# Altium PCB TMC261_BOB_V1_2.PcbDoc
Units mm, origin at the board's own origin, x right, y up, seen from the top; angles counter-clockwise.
Board outline 38.1 x 25.4 mm, 4 copper layers (Top, GND1, GND2, Bottom), stack 0.704 mm thick; 27 components, 23 nets, 90 pads, 69 vias.
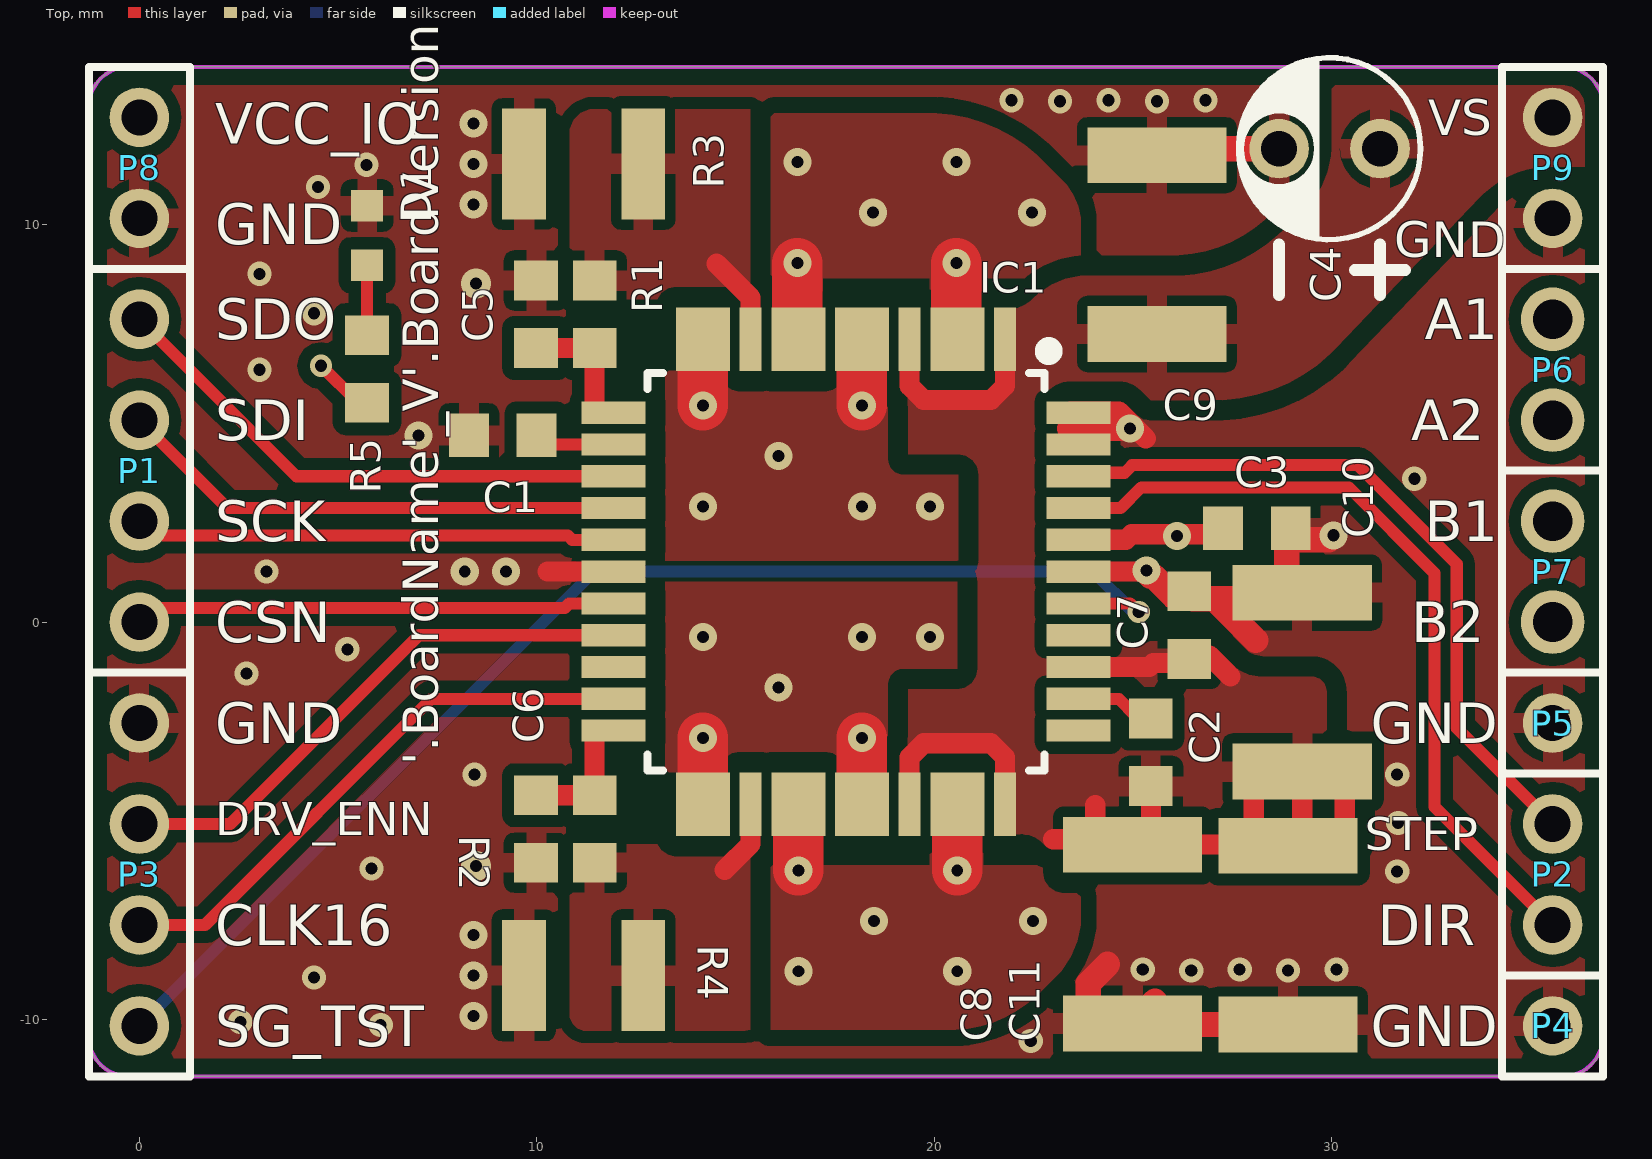
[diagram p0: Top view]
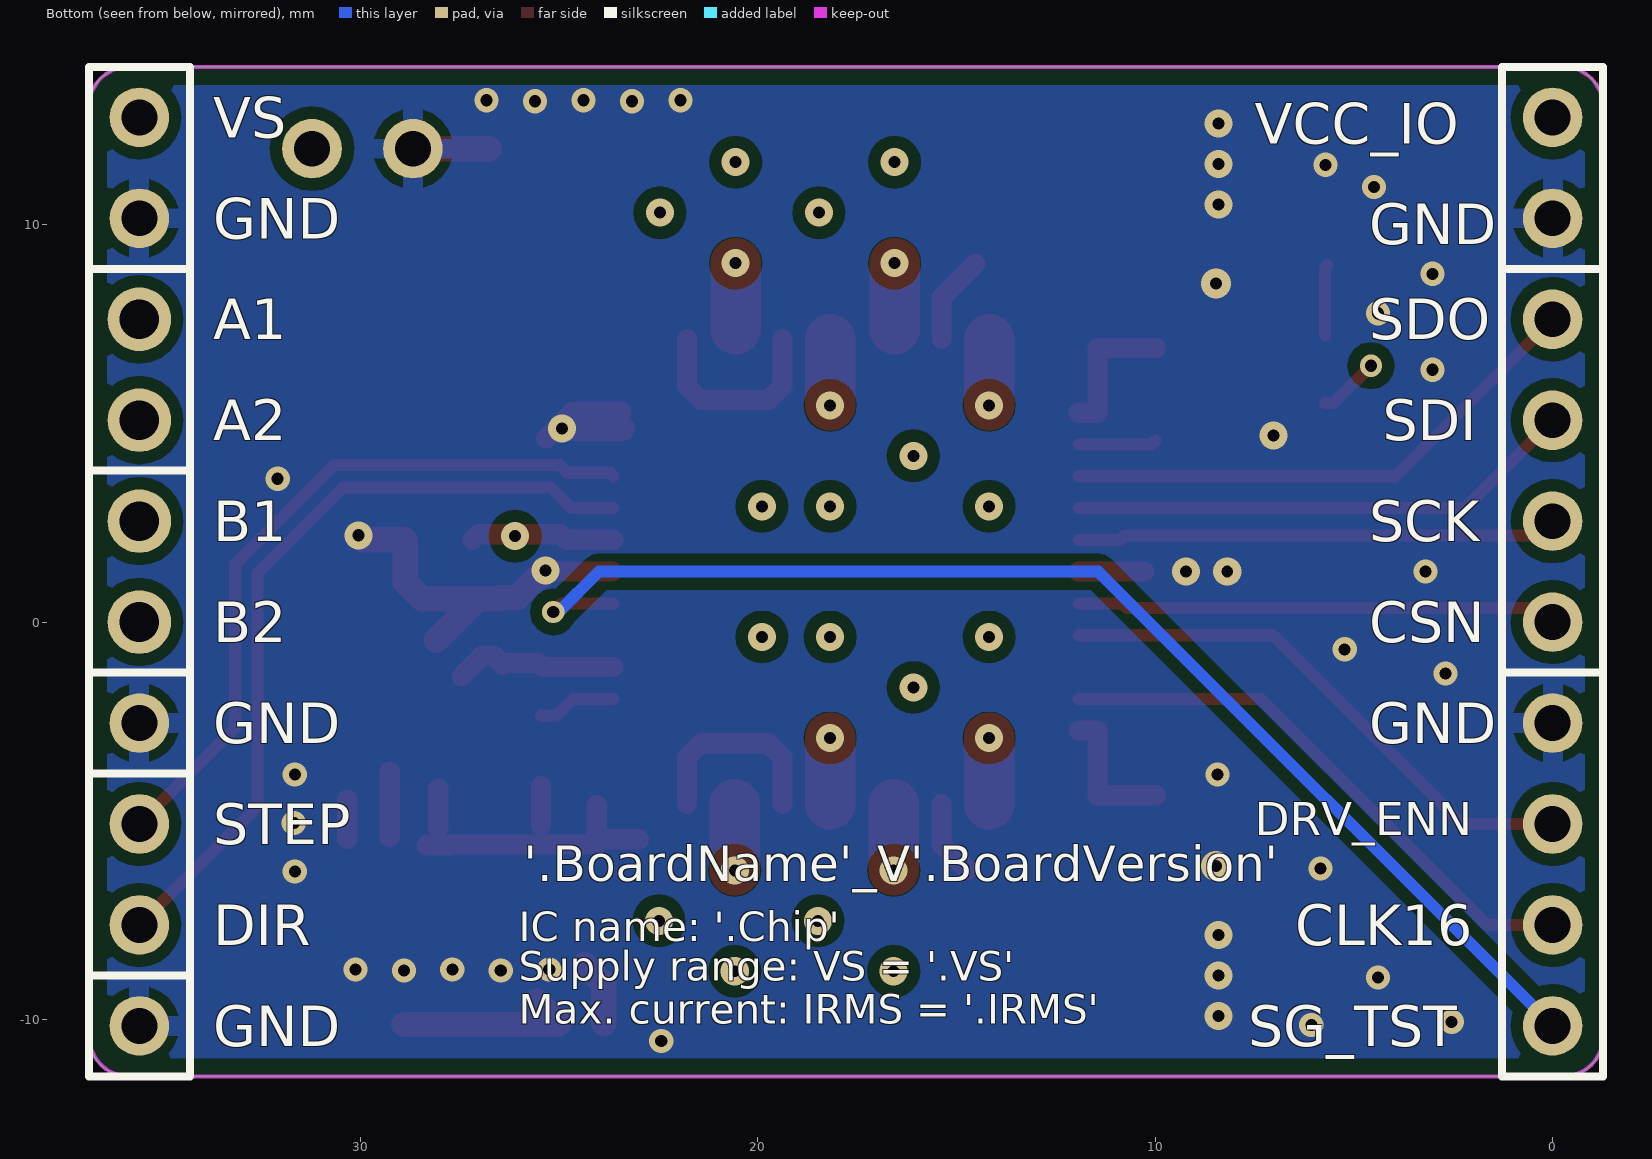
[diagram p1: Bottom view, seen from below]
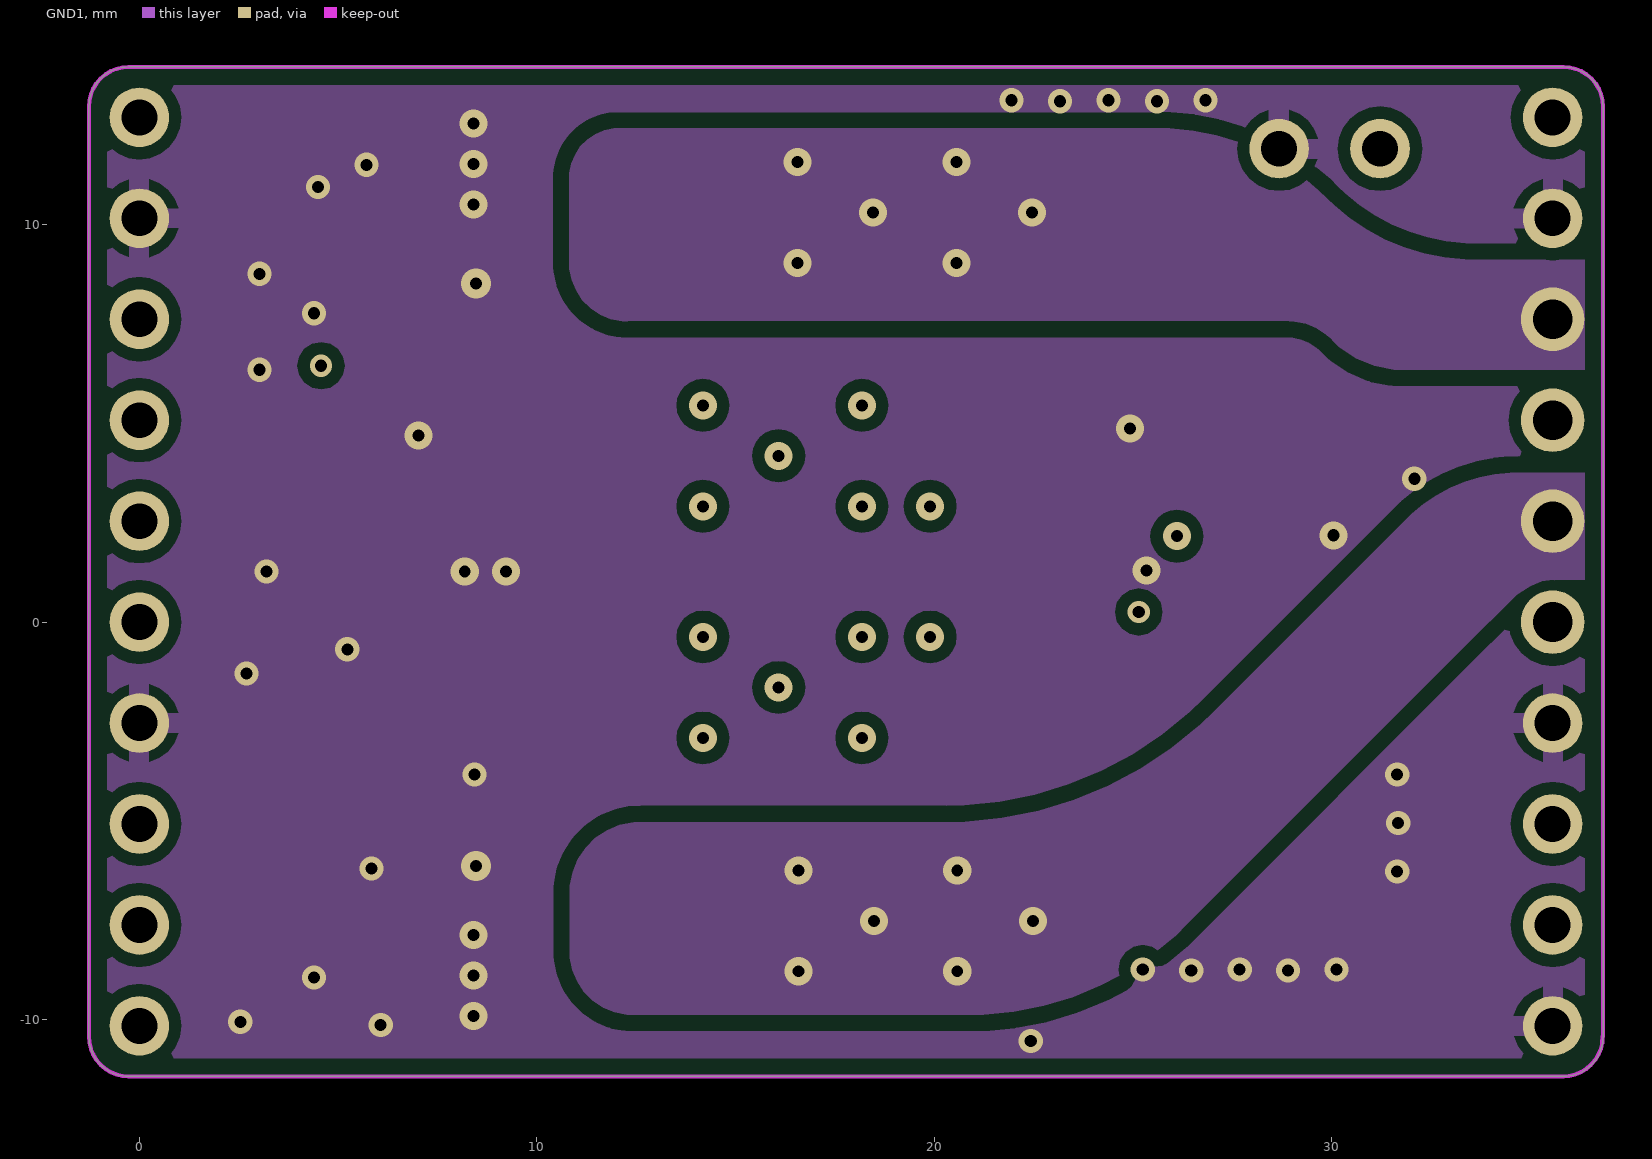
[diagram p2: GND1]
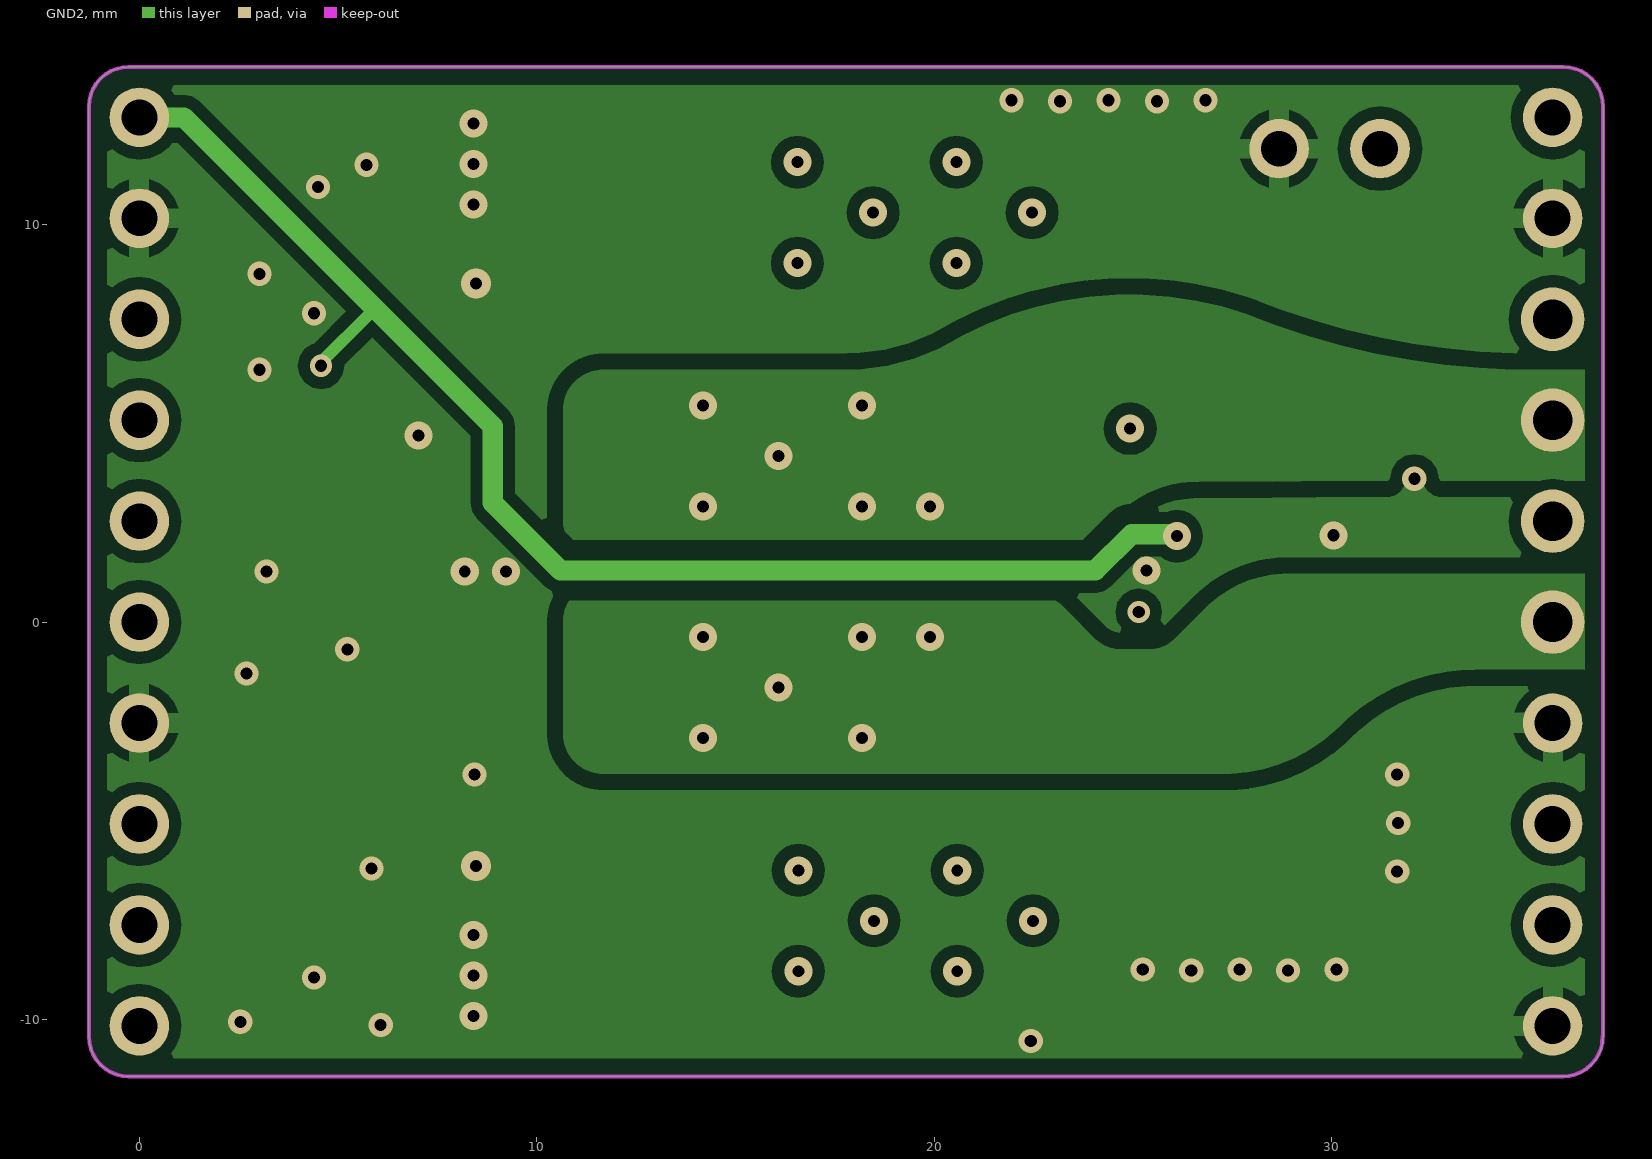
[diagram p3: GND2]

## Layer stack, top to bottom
Top Solder: solder mask 0.0102, Solder Resist, Dk 3.5
Top: signal copper 0.035
Dielectric 1: core 0.2, FR-4, Dk 4.8
GND1: signal copper 0.0175
Dielectric 2: prepreg 0.127, FR-4, Dk 4.2
GND2: signal copper 0.0356
Dielectric4: core 0.254, FR-4, Dk 4.2
Bottom: signal copper 0.035
Bottom Solder: solder mask 0.0102, Solder Resist, Dk 3.5

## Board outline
-1.27,-10.43 -1.27,12.97 cw(c-0.27,12.97) -0.27,13.97 35.83,13.97 cw(c35.83,12.97) 36.83,12.97 36.83,-10.43 cw(c35.83,-10.43) 35.83,-11.43 -0.27,-11.43 cw(c-0.27,-10.43)

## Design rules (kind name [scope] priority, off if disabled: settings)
Clearance Motor_Output_to_GND_Clearance [InNetClass('MotorOutput') vs InNet('GND')] p1: gap=0.305 ignorepadtopadclearanceinfootprint=TRUE except(0: Arc-Hole Track-Hole SMDPad-Hole THPad-Hole Via-Hole Fill-Hole Poly-Hole Region-Hole Text-Hole; 0.406: Fill-Fill Fill-Poly Fill-Region Poly-Poly Poly-Region Region-Region)
Clearance BoardOutlineClearance [OnLayer('Keep-Out Layer')] p2: gap=0.4 ignorepadtopadclearanceinfootprint=FALSE except(0: Arc-Hole Track-Hole SMDPad-Hole THPad-Hole Via-Hole Fill-Hole Poly-Hole Region-Hole Text-Hole)
Clearance PinheaderToKeepoutClearance [InComponentClass('Pinheader') vs OnLayer('Keep-Out Layer')] p3: gap=0.203 ignorepadtopadclearanceinfootprint=FALSE except(0: Arc-Hole Track-Hole SMDPad-Hole THPad-Hole Via-Hole Fill-Hole Poly-Hole Region-Hole Text-Hole)
Clearance IC1_Clearance_PadToPad_1 [InComponent('IC1') and IsPad vs InComponent('IC1') and IsPad] p4: gap=0.152 ignorepadtopadclearanceinfootprint=FALSE except(0: Arc-Hole Track-Hole SMDPad-Hole THPad-Hole Via-Hole Fill-Hole Poly-Hole Region-Hole Text-Hole)
Clearance IC1_PintoTraceClearance [InComponent('IC1') and IsPad vs Istrack] p5: gap=0.254 ignorepadtopadclearanceinfootprint=FALSE except(0: Arc-Hole Track-Hole SMDPad-Hole THPad-Hole Via-Hole Fill-Hole Poly-Hole Region-Hole Text-Hole)
Clearance MotorOutput_Clearance_1 [InNetClass('MotorOutput') vs OnLayer('Keep-Out Layer') AND IsWire and (not OnLayer('GND1')) and (not OnLayer('GND2'))] p6: gap=0.305 ignorepadtopadclearanceinfootprint=TRUE except(0: Arc-Hole Track-Hole SMDPad-Hole THPad-Hole Via-Hole Fill-Hole Poly-Hole Region-Hole Text-Hole)
Clearance MotorOutput_Clearance [InNetClass('MotorOutput') vs not (OnLayer('Keep-Out Layer') and InComponent('IC1') and IsPad)] p7: gap=0.508 ignorepadtopadclearanceinfootprint=TRUE except(0: Arc-Hole Track-Hole SMDPad-Hole THPad-Hole Via-Hole Fill-Hole Poly-Hole Region-Hole Text-Hole; 0.152: Track-Track; 0.254: THPad-Poly)
Clearance VM_Clearance [InNet('+VS') AND (NOT IsPad) vs not (InComponent('IC1'))] p8: gap=0.508 ignorepadtopadclearanceinfootprint=TRUE except(0: Arc-Hole Track-Hole SMDPad-Hole THPad-Hole Via-Hole Fill-Hole Poly-Hole Region-Hole Text-Hole; 0.29: Track-Track; 0.3: SMDPad-Poly)
Clearance "Fiducial Clearance" [HasFootprint('FIDUCIAL_40MIL')] p9 off: gap=0.66 ignorepadtopadclearanceinfootprint=FALSE except(0: Arc-Hole Track-Hole SMDPad-Hole THPad-Hole Via-Hole Fill-Hole Poly-Hole Region-Hole Text-Hole)
Clearance "Mounting Hole Clearance" [(HoleDiameter >= 110) And  IsPad  And ((PadYSize_AllLayers - HoleDiameter)  <=  1)] p10 off: gap=0.762 ignorepadtopadclearanceinfootprint=FALSE except(0: Arc-Hole Track-Hole SMDPad-Hole THPad-Hole Via-Hole Fill-Hole Poly-Hole Region-Hole Text-Hole)
Clearance [All vs NOT InComponent('IC1')] p11: gap=0.305 ignorepadtopadclearanceinfootprint=FALSE except(0: Arc-Hole Track-Hole SMDPad-Hole THPad-Hole Via-Hole Fill-Hole Poly-Hole Region-Hole Text-Hole; 0.254: Track-Track)
ComponentClearance IC1_to_series_sense_resistors_Clearance [inComponent('IC1') vs inComponent('R1') or inComponent('R2')] p1: gap=0 collisioncheckmode=3 verticalgap=2540 showdistances=FALSE
ComponentClearance Pinheader2PinheaderClearance [InComponentClass('Pinheader') vs InComponentClass('Pinheader')] p2: gap=0 collisioncheckmode=3 verticalgap=0 showdistances=FALSE
ComponentClearance [All] p3: gap=0.254 collisioncheckmode=3 verticalgap=0.102 showdistances=FALSE
DiffPairsRouting [All] p1 off: maxlimit=0.254 minlimit=0.191 mostfreqgap=0.254 toplayer_prefgap=0.191 toplayer_minwidth=0.191 toplayer_maxwidth=0.191 toplayer_prefwidth=0.191 midlayer1_prefgap=0.191 midlayer1_minwidth=0.191 midlayer1_maxwidth=0.191 midlayer1_prefwidth=0.191 midlayer2_mingap=0.254 midlayer2_minwidth=0.381 midlayer2_maxwidth=0.381 midlayer2_prefwidth=0.381 bottomlayer_prefgap=0.191 bottomlayer_minwidth=0.191 bottomlayer_maxwidth=0.191 bottomlayer_prefwidth=0.191 maxuncoupledlength=12.7
HoleSize [All] p1: absolutevalues=TRUE maxlimit=2540 minlimit=0.3 maxpercent=80.000 minpercent=20.000
HoleToHoleClearance [All] p1: gap=0.203 allowstackedmicrovias=TRUE
MatchedLengths "SD_CARD MatchedLengths" [InNetClass('SD_CARD')] p1: tolerance=0.254 checknetsindiffpair=FALSE checkdiffpairvsdiffpair=TRUE checkxsignals=TRUE checkothers=TRUE
MinimumAnnularRing MinimumViaAnnualRing [All] p1: minimumring=0.125
MinimumSolderMaskSliver STM32_MinimumSolderMaskSliver [(InComponent('STM1') AND InComponent('STM2')) vs (InComponent('STM1') AND InComponent('STM2'))] p1: minsoldermaskwidth=0.025
MinimumSolderMaskSliver USB_HUB_MinimumSolderMaskSliver [InComponent('USB_HUB')] p2: minsoldermaskwidth=0.025
MinimumSolderMaskSliver [All] p3 off: minsoldermaskwidth=0.038
PasteMaskExpansion TestPadPasteMaskExpansion [HasFootprint('SMD_TP_2X2_ROUND')] p1: expansion=-2
PasteMaskExpansion [All] p2: expansion=0
PolygonConnect VM_IC1_ConnectStyle [InNet('+VS') AND (InComponent('IC1') or InComponent('P9'))] p1: connectstyle=Direct reliefconductorwidth=0.508 reliefentries=4 polygonreliefangle="90 Angle" airgapwidth=0.203
PolygonConnect VM_ViaConnectStyle_1 [InNet('VM') AND IsVia] p2: connectstyle=Direct reliefconductorwidth=0.508 reliefentries=4 polygonreliefangle="90 Angle" airgapwidth=0.203
PolygonConnect MotorPowerConnectStyle [InNetClass('MotorOutput') vs not IsTrack] p3: connectstyle=Direct reliefconductorwidth=0.254 reliefentries=4 polygonreliefangle="90 Angle" airgapwidth=0.254
PolygonConnect ThermalVias [IsVia] p4: connectstyle=Direct reliefconductorwidth=0.254 reliefentries=4 polygonreliefangle="90 Angle" airgapwidth=0.254
PolygonConnect [All] p5: connectstyle=Relief reliefconductorwidth=0.508 reliefentries=4 polygonreliefangle="90 Angle" airgapwidth=0.254
RoutingVias GND_RoutingVias [InNet('GND')] p1: holewidth=0.305 width=0.706 viastyle="Through Hole" minholewidth=0.305 minwidth=0.559 maxholewidth=0.305 maxwidth=1.27
RoutingVias [All] p2: holewidth=0.305 width=0.559 viastyle="Through Hole" minholewidth=0.305 minwidth=0.559 maxholewidth=0.305 maxwidth=1.27
ShortCircuit [All] p1 off: allowed=FALSE
SilkToBoardRegionClearance [All] p1 off:
SilkToSilkClearance [All] p1 off: silktosilkclearance=0.254
SilkToSolderMaskClearance [IsPad] p1 off: minsilkscreentomaskgap=0.254 clearancetoexposedcopper=TRUE
SolderMaskExpansion FiducialSolderMaskExpansion [HasFootprint('FIDUCIAL_40MIL')] p1: expansion=0.66
SolderMaskExpansion [All] p2: expansion=0.102
UnRoutedNet [All] p1 off:
Width Other_Width [All] p1: maxlimit=2540 minlimit=0.203 preferedwidth=0.3 minimp=50.000000 maximp=50.000000 favimp=50.000000
19 further rules are at their usual default settings.

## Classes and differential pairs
net class MotorOutput: OA1 OA2 OB1 OB2
differential pair class USB_DIFF: STM_USB STM_USB_D
component class Pinheader: P1 P2 P3 P4 P5 P6 P7 P8 P9

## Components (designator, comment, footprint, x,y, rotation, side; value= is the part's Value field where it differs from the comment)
C1 "470nF/16V/10%" C0603 9.144,4.699 r180 top
C2 "100nF/100V/10%" C0603 25.451,-3.277 r270 top
C3 "100nF/50V/20%" C0603 28.118,2.362 r180 top
C4 "Cap Pol1" EXT_POL_CAP_FLIPPED 31.217,11.913 r90 top value=TBD
C5 "10nF/100V/10%" C0603 9.982,7.747 r270 top
C6 "10nF/100V/10%" C0603 9.982,-5.207 r90 top
C7 "100nF/100V/10%" C0603 26.416,-0.076 r270 top
C8 "10uF/100V/20%" CKG45NX7S2A106M500JH 24.994,-7.849 r90 top
C9 "10uF/100V/20%" CKG45NX7S2A106M500JH 25.603,9.5 r270 top
C10 "10uF/100V/20%" CKG45NX7S2A106M500JH 29.261,-1.508 r270 top
C11 "10uF/100V/20%" CKG45NX7S2A106M500JH 28.905,-7.874 r90 top
D1 "LED, Blue, SMD, 20mA, 2.8V, 465 nm" LED_0603 5.73,9.728 r90 top
IC1 "TMC261" TMC26X_PQFP44_0.8_10X10_TMC236 17.78,1.27 r180 top value=TMC261-PA
P1 "SPI" 4_PIN_THT 0,0 r0 top
P2 "STEP/DIR" 2_PIN_THT 35.56,-5.08 r180 top
P3 "MISC" 4_PIN_THT 0,-10.16 r0 top
P4 "GND" TH_PIN 35.56,-10.16 r0 top
P5 "GND" TH_PIN 35.56,-2.54 r0 top
P6 "OA" 2_PIN_THT_1MM_HOLE 35.56,5.08 r0 top
P7 "OB" 2_PIN_THT_1MM_HOLE 35.56,0 r0 top
P8 "VCC_IO" 2_PIN_THT 0,10.16 r0 top
P9 "VM" 2_PIN_THT 35.56,10.16 r0 top
R1 "10R / 100mW / 1%" R0603 11.455,7.747 r270 top
R2 "10R / 100mW / 1%" R0603 11.455,-5.207 r90 top
R3 ".15R / 1W / 1%" R1210 11.176,11.528 r0 top
R4 ".15R / 1W / 1%" R1210 11.176,-8.89 r0 top
R5 "1k" R0603 5.73,6.367 r90 top

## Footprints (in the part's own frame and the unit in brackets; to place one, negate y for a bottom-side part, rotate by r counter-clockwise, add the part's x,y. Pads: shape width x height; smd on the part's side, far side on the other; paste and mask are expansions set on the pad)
2_PIN_THT [mm]
  round 1.5 hole 0.9: 1(0,0) 2(0,2.54)
  silkscreen extent -1.27,-1.27 1.27,3.81
2_PIN_THT_1MM_HOLE [mm]
  round 1.6 hole 1: 1(0,0) 2(0,2.54)
  silkscreen extent -1.27,-1.27 1.27,3.81
4_PIN_THT [mm]
  round 1.5 hole 0.9: 1(0,0) 2(0,2.54) 3(0,5.08) 4(0,7.62)
  silkscreen extent -1.27,-1.27 1.27,8.89
C0603 [mm] "0603 ceramic capacitor"
  rect 1x1.1 smd: 1(-0.85,0) 2(0.85,0)
  body extent -0.8,-0.4 0.8,0.4, height 0.8
CKG45NX7S2A106M500JH [mm] "1812 STACKED capacitor"
  rect 1.4x3.5 smd: 1(-2.25,0) 2(2.25,0)
  body extent -2.5,-1.6 2.5,1.6, height 3.35
EXT_POL_CAP_FLIPPED [mm]
  round 1.5 hole 0.9: 1(0,0) 2(0,2.54)
  silkscreen extent -3.68,-1.02 2.29,3.56
LED_0603 [mm]
  rect 0.8x0.8 smd: 1(-0.75,0) 2(0.75,0)
  body extent -0.8,-0.38 0.85,0.35, height 0.68
R0603 [mm] "0603 resistor"
  rect 1x1.1 smd: 1(-0.85,0) 2(0.85,0)
  body extent -0.8,-0.4 0.8,0.4, height 0.45
R1210 [mm] "1210 resistor"
  rect 1.1x2.8 smd: 1(-1.5,0) 2(1.5,0)
  body extent -1.6,-1.25 1.6,1.25, height 0.59
TH_PIN [mm]
  round 1.5 hole 0.9: 1(0,0)
  silkscreen extent -1.27,-1.27 1.27,1.27
TMC26X_PQFP44_0.8_10X10_TMC236 [mm]
  rect 0.56x1.6 smd: 1(-4,-5.85) 4(-1.6,-5.85) 9(2.4,-5.85) 25(2.4,5.85) 30(-1.6,5.85) 33(-4,5.85)
  rect 1.36x1.6 smd: 2(-2.8,-5.85) 5(-0.4,-5.85) 7(1.2,-5.85) 10(3.6,-5.85) 23(3.6,5.85) 26(1.2,5.85) 28(-0.4,5.85) 31(-2.8,5.85)
  rect 1.6x0.56 smd: 12(5.85,-4) 13(5.85,-3.2) 14(5.85,-2.4) 15(5.85,-1.6) 16(5.85,-0.8) 17(5.85,0) 18(5.85,0.8) 19(5.85,1.6) 20(5.85,2.4) 21(5.85,3.2) 22(5.85,4) 34(-5.85,4) 35(-5.85,3.2) 36(-5.85,2.4) 37(-5.85,1.6) 38(-5.85,0.8) 39(-5.85,0) 40(-5.85,-0.8) 41(-5.85,-1.6) 42(-5.85,-2.4) 43(-5.85,-3.2) 44(-5.85,-4)
  silkscreen extent -5.2,-5.65 5,5, body extent -5,-5 5,5, height 1.6

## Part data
C1: library part Capacitor, "Ceramic capacitor", Capacitance=470nF, MPN=MC0603X474K160CT, VoltageRating=16V
C2 C7: library part "0.1 µF, 100 V, ± 10%, X7R, GRM Series", "SMD Multilayer Ceramic Capacitor, 0603 [1608 Metric], 0.1 µF, 100 V, ± 10%, X7R, GRM Series", Capacitance=100nF, MPN=GRM188R72A104KA35D, VoltageRating=100V
C3: library part Capacitor, "Ceramic capacitor", Capacitance=100nF, MPN=MC0603F104M500CT, VoltageRating=50V
C4: "Polarized Capacitor (Radial)"
C5 C6: library part "SMD Multilayer Ceramic Capacitor, 0603 [1608 Metric], 0.01 µF, 100 V, ± 10%, X7R, MC Series", "Ceramic capacitor", Capacitance=10nF, MPN=MC0603B103K101CT, VoltageRating=100V
C8 C9 C10 C11: library part "10 µF, 100 V, ± 20%, X7S, CKG Series", "SMD Multilayer Ceramic Capacitor, 1812 [4532 Metric], 10 µF, 100 V, ± 20%, X7S, CKG Series", Capacitance=10uF, MPN=CKG45NX7S2A106M500JH, VoltageRating=100V
D1: Colour=Blue, Current rating=20mA, MPN=LTST-C191TBKT-5A
IC1: library part TMC261-PA, "coolStep™ driver with Step/Dir Interface and SPI, up to 30V,  internal MOSFET for up to 4 A, PQFP-44", Manufacturer=TRINAMIC
P1 P3: library part "Header 4", "Header, 4-Pin"
P2 P6 P7 P8 P9: library part "Header 2", "Header, 2-Pin"
P4 P5: library part PIN
R1 R2: library part "RES SMD 10 OHM 75V 1% 0603", "0.1 Ohm ±1% 1W Chip Resistor 1210 (3225 Metric) Automotive AEC-Q200, Current Sense, Moisture Resistant Thick Film", MPN=MCMR06X10R0FTL, PowerRating=100mW, Resistance=10R, Temp coefficient=*ppm, VoltageRating=75V
R3 R4: library part "RES SMD 0.15 OHM 1% 1W 1210", "0.15 Ohm ±1% 1W Chip Resistor 1210 (3225 Metric) Automotive AEC-Q200, Current Sense, Moisture Resistant Thick Film", MPN=RCWE1210R150FKEA, PowerRating=1W, Resistance=.15R, Temp coefficient=*ppm, VoltageRating=50V
R5: library part "1 kohm, 50 V, 0603 [1608 Metric], 63 mW, ± 1%, MC Series", "1 kohm, 50 V, 0603 [1608 Metric], 63 mW, ± 1%, MC Series", MPN=MC0063W060311K, PowerRating=63mW, Temp coefficient=*ppm, VoltageRating=50V

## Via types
v1: diameter 0.706, hole 0.3, Top to Bottom, tented both sides, 35 vias
v2: diameter 0.61, hole 0.305, Top to Bottom, tented both sides, 28 vias
v3: diameter 0.706, hole 0.305, Top to Bottom, tented both sides, 2 vias
v4: diameter 0.757, hole 0.3, Top to Bottom, tented both sides, 2 vias
v5: diameter 0.559, hole 0.305, Top to Bottom, tented both sides, 2 vias

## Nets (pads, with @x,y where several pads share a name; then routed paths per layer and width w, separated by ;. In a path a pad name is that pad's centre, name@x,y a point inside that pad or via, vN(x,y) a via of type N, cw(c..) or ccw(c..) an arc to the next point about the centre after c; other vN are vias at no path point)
+VS: C2.2 C4.1 C7.2 C8.2 C9.2 C10.2 C11.2 IC1.1 IC1.4 IC1.30 IC1.33 IC1.36 P9.2 | length 25.6
  Top w0.508: IC1.30 19.38,-3.4 19.732,-3.048 21.428,-3.048 21.78,-3.4 IC1.33 ; IC1.4 19.38,5.94 19.732,5.588 21.428,5.588 21.78,5.94 IC1.1 ; 22.99,-5.466 C8.2@23.803,-5.466 ; IC1.36 25.408,-1.13 25.509,-1.029 C7.2@26.416,-1.029 ; 24.054,-4.608 24.054,-5.599 C11.2@27.737,-5.599 ; C8.2@25.451,-5.117 C2.2 ; C7.2@26.416,-1.079 26.656,-0.838 26.924,-0.838 27.457,-1.372 ; C11.2@28.042,-5.182 C10.2@28.042,-4.191 ; C11.2@29.261,-5.41 C10.2 ; C11.2@30.328,-5.461 30.328,-4.47 ; C11.2@27.737,-5.599 27.762,-5.624 28.336,-5.624 28.336,-5.614 28.321,-5.599 C11.2@27.737,-5.599
BRA: IC1.9 R1.1 R3.2 | length 2.3
  Top w0.508: 14.525,9.017 15.38,8.162 IC1.9
BRB: IC1.25 R2.1 R4.2 | length 1.9
  Top w0.508: 14.728,-6.235 15.38,-5.582 IC1.25
CLK16: IC1.21 P3.2 | length 14.3
  Top w0.305: P3.2 1.651,-7.62 7.341,-1.93 IC1.21
CSN: IC1.18 P1.1 | length 12.1
  Top w0.305: P1.1 0.356,0.356 10.702,0.356 10.816,0.47 IC1.18
DIR: IC1.41 P2.2 | length 20.1
  Top w0.305: IC1.41 24.692,2.87 25.212,3.39 30.429,3.39 32.588,1.231 32.588,-4.648 P2.2
DRV_ENN: IC1.19 P3.3 | length 13.9
  Top w0.305: P3.3 2.286,-5.08 7.036,-0.33 IC1.19
GND: C1.2 C3.1 C4.2 C5.1 C6.1 C7.1 C8.1 C9.1 C10.1 C11.1 D1.2 IC1.17 IC1.39 IC1.43 IC1.44 P3.4 P4.1 P5.1 P8.1 P9.1 R3.1 R4.1 | length 23.1
  Top w0.508: 10.27,1.27 IC1.17 ; IC1.44@23.427,5.295 24.651,5.295 25.324,4.623 ; IC1.39@23.666,1.27 v3@25.332,1.27
  Top w0.635: 23.404,4.87 v1(24.93,4.87) ; C8.1@23.876,-10.109 23.876,-9.093 24.359,-8.611 ; v3@25.332,1.27 25.446,1.156 25.519,1.156 26.048,0.627 26.048,0.621 C7.1@26.416,0.621 ; C8.1@25.552,-9.54 C8.1 25.019,-10.124 C11.1 ; C7.1@26.467,0.621 26.503,0.586 27.05,0.586 ; C9.1@26.748,11.913 C4.2 ; 28.092,-0.457 27.05,0.586 ; v3(30.048,2.184) 29.934,2.07 28.872,2.07 28.872,1.009 28.448,0.586 27.05,0.586
  other v1: 8.406,-9.906 8.406,-8.89 8.406,-7.874 8.187,1.27 9.228,1.27 7.024,4.699 8.406,10.512 8.406,11.528 8.406,12.544
  other v2: 22.428,-10.541 6.071,-10.135 2.54,-10.058 4.394,-8.941 26.467,-8.767 28.905,-8.767 25.248,-8.742 27.686,-8.742 30.124,-8.742 31.648,-6.273 5.842,-6.198 31.674,-5.055 8.433,-3.835 31.648,-3.835 2.692,-1.295 5.232,-0.686 3.2,1.27 32.08,3.607 3.023,6.35 4.394,7.772 3.023,8.763 4.496,10.947 5.715,11.506 23.165,13.106 25.603,13.106 21.946,13.132 24.384,13.132 26.822,13.132
  other v3: 25.343,1.298
  other v4: 8.465,-6.138 8.465,8.516
NetC1_1: C1.1 IC1.13 | length 2
  Top w0.305: C1.1@9.994,4.572 10.096,4.47 IC1.13
NetC2_1: C2.1 IC1.35 | length 2
  Top w0.305: IC1.35 24.646,-1.93 25.066,-2.35 C2.1@25.451,-2.35
NetD1_1: D1.1 R5.2 | length 1.8
  Top w0.305: D1.1@5.664,8.978 5.73,8.912 R5.2
OA1: IC1.2 IC1.7 P6.2 | length 3.3
  Top w1.27: IC1.7@16.557,7.366 v1(16.557,9.032) ; IC1.2@20.557,7.366 v1(20.557,9.032)
  other v1: 18.462,10.302 22.462,10.302 16.557,11.572 20.557,11.572
OA2: IC1.5 IC1.10 P6.1 | length 3.3
  Top w1.27: v1(14.18,5.454) IC1.10 ; v1(18.18,5.454) IC1.5
  other v1: 14.18,2.914 18.18,2.914 19.895,2.914 16.085,4.184
OB1: IC1.26 IC1.31 P7.2 | length 3.3
  Top w1.27: v1(16.58,-6.246) IC1.26 ; v1(20.58,-6.246) IC1.31
  other v1: 16.58,-8.786 20.58,-8.786 18.485,-7.516 22.485,-7.516
OB2: IC1.23 IC1.28 P7.1 | length 3.3
  Top w1.27: IC1.23 v1(14.18,-2.914) ; IC1.28 v1(18.18,-2.914)
  other v1: 16.085,-1.644 14.18,-0.374 18.18,-0.374 19.895,-0.374
SCK: IC1.16 P1.2 | length 12.1
  Top w0.305: P1.2 0.254,2.54 0.61,2.184 10.778,2.184 10.892,2.07 IC1.16
SDI: IC1.15 P1.3 | length 12.8
  Top w0.305: P1.3 2.21,2.87 IC1.15
SDO: IC1.14 P1.4 | length 13.6
  Top w0.305: P1.4 3.95,3.67 IC1.14
SG_TST: IC1.38 P3.1 | length 32.3
  Top w0.305: IC1.38 24.93,0.47 v5(25.146,0.254)
  Bottom w0.305: P3.1@0.42,-10.16 P3.1 11.43,1.27 23.999,1.27 25.015,0.254 v5(25.146,0.254)
SRA: C5.2 IC1.12 R1.2 | length 3.6
  Top w0.508: C5.2 R1.2 11.455,5.27 IC1.12
SRB: C6.2 IC1.22 R2.2 | length 3.6
  Top w0.508: C6.2 R2.2 11.455,-2.73 IC1.22
STEP: IC1.42 P2.1 | length 18.2
  Top w0.305: IC1.42 23.719,3.759 24.79,3.759 24.98,3.949 30.661,3.949 33.147,1.462 33.147,-2.667 P2.1
VCC_IO: C3.2 IC1.40 P8.2 R5.1 | length 39.4
  Top w0.305: v5(4.572,6.452) 5.506,5.517 R5.1
  Top w0.508: IC1.40 24.825,2.07 24.965,2.21 27.032,2.21 C3.2@27.172,2.07
  GND2 w0.305: v5(4.572,6.452) 4.572,6.537 5.831,7.796
  GND2 w0.508: P8.2 1.119,12.7 8.89,4.929 8.89,3.004 10.594,1.3 24.056,1.3 24.965,2.21 26.057,2.21 v1(26.105,2.161)
pads on no net: IC1.20 IC1.34 IC1.37

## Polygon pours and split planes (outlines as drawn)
GND on GND2 "GND2_GND" (solid, pour order 28): -1.27,-10.43 -1.27,12.97 cw(c-0.27,12.97) -0.27,13.97 35.83,13.97 cw(c35.83,12.97) 36.83,12.97 36.83,-10.43 cw(c35.83,-10.43) 35.83,-11.43 -0.27,-11.43 cw(c-0.27,-10.43)
OA2 on GND2 "GND1_OA2" (solid, pour order 17): 36.83,3.556 29.607,3.556 cw(c27.512,99.154) 26.653,3.537 ccw(c26.627,0.695) 24.575,2.661 cw(c-21.704,46.978) 24.193,2.265 cw(c22.426,3.986) 22.426,1.52 11.688,1.52 cw(c11.688,2.54) 10.668,2.54 10.668,5.334 cw(c11.684,5.334) 11.684,6.35 17.821,6.35 ccw(c17.821,11.567) 20.413,7.04 cw(c24.915,-0.823) 28.187,7.625 ccw(c35.012,25.248) 35.012,6.35 36.83,6.35
OB2 on GND2 "GND1_OB2" (solid, pour order 16): 11.688,1.029 ccw(c11.688,0.009) 10.668,0.009 10.668,-2.81 ccw(c11.675,-2.81) 11.675,-3.818 19.918,-3.818 27.267,-3.818 ccw(c27.267,0.363) 30.224,-2.593 cw(c33.602,-5.971) 33.602,-1.194 36.83,-1.194 36.83,1.216 28.906,1.216 ccw(c28.906,-1.722) 26.828,0.356 26.043,-0.429 cw(c25.424,0.189) 25.424,-0.686 24.695,-0.686 cw(c24.695,0.236) 24.044,-0.416 23.343,0.285 ccw(c21.547,-1.51) 21.547,1.029
GND on GND1 "GND_GND" (solid, pour order 30): -1.27,-10.43 -1.27,12.97 cw(c-0.27,12.97) -0.27,13.97 35.83,13.97 cw(c35.83,12.97) 36.83,12.97 36.83,-10.43 cw(c35.83,-10.43) 35.83,-11.43 -0.27,-11.43 cw(c-0.27,-10.43)
OB1 on GND1 "GND1_OB1" (solid, pour order 27): 10.83,-8.286 10.83,-6.811 cw(c12.611,-6.811) 12.611,-5.03 20.312,-5.03 ccw(c20.312,4.487) 27.042,-2.242 31.875,2.591 cw(c34.695,-0.228) 34.695,3.759 37.22,3.759 37.22,1.064 35.709,1.064 ccw(c35.709,-0.59) 34.539,0.579 33.401,-0.559 26.354,-7.606 cw(c20.863,-2.115) 20.863,-9.881 12.425,-9.881 cw(c12.425,-8.286)
OA1 on GND1 "GND1_OA1" (solid, pour order 26): 10.82,11.176 10.82,9.042 ccw(c12.293,9.042) 12.293,7.57 13.53,7.57 28.928,7.57 cw(c28.928,6.094) 29.972,7.137 30.015,7.094 ccw(c31.812,8.89) 31.812,6.35 36.83,6.35 36.83,9.119 33.602,9.119 cw(c33.602,14.39) 29.874,10.663 ccw(c25.63,6.419) 25.63,12.421 12.065,12.421 ccw(c12.065,11.176)
GND on Bottom "BTM_GND" (solid, pour order 29): -1.27,-10.43 -1.27,12.97 cw(c-0.27,12.97) -0.27,13.97 35.83,13.97 cw(c35.83,12.97) 36.83,12.97 36.83,-10.43 cw(c35.83,-10.43) 35.83,-11.43 -0.27,-11.43 cw(c-0.27,-10.43)
OA1 on Top "TOP_OB1" (solid, pour order 24): 15.73,6.426 15.73,12.802 19.864,12.802 cw(c19.864,8.758) 22.724,11.617 23.226,11.115 cw(c22.127,10.016) 23.681,10.016 23.681,8.653 21.234,8.653 21.234,6.426 19.888,6.426 19.888,8.653 17.196,8.653 17.196,6.426
GND on Top "TOP_GND" (solid, pour order 31): -1.27,-10.43 -1.27,12.97 cw(c-0.27,12.97) -0.27,13.97 35.83,13.97 cw(c35.83,12.97) 36.83,12.97 36.83,-10.43 cw(c35.83,-10.43) 35.83,-11.43 -0.27,-11.43 cw(c-0.27,-10.43)
OB1 on Top "TOP_OB1" (solid, pour order 25): 15.73,-3.886 15.73,-10.262 20.378,-10.262 ccw(c20.378,-7.03) 22.663,-9.315 23.049,-8.93 ccw(c21.524,-7.404) 23.681,-7.405 23.681,-6.113 21.234,-6.113 21.234,-3.886 19.888,-3.886 19.888,-6.113 17.196,-6.113 17.196,-3.886
BRB on Top "TOP_BRB" (solid, pour order 18): 15.367,-5.922 15.367,-10.283 11.256,-10.283 cw(c11.256,-9.861) 10.834,-9.861 10.834,-6.731 cw(c11.977,-6.731) 11.977,-5.588 15.033,-5.588
OB2 on Top "TOP_OB2" (solid, pour order 20): 13.53,-3.78 13.233,-3.78 13.233,1.02 20.574,1.02 20.574,-1.168 19.228,-1.168 ccw(c19.228,-1.566) 18.83,-1.566 18.83,-3.78
OA2 on Top "TOP_OA2" (solid, pour order 21): 13.53,6.32 13.233,6.32 13.233,1.52 20.599,1.52 20.599,3.708 19.228,3.708 cw(c19.228,4.106) 18.83,4.106 18.83,6.32
+VS on Top "TOP_VM" (solid, pour order 22): 19.177,-5.334 18.288,-4.445 18.288,-2.159 18.288,7.189 18.669,7.57 18.973,7.874 21.844,7.874 ccw(c21.844,8.793) 22.494,8.143 cw(c23.867,6.769) 23.868,8.712 25.991,8.712 ccw(c25.991,12.683) 28.798,9.875 29.387,10.464 ccw(c27.912,11.938) 29.997,11.938 29.997,13.51 36.373,13.51 36.373,11.455 35.528,11.455 ccw(c35.527,8.954) 33.718,10.681 30.112,6.903 cw(c27.039,9.836) 27.043,5.588 23.062,5.585 23.062,-0.483 26.919,-0.483 27.428,-1.018 ccw(c28.253,-0.233) 28.253,-1.372 29.489,-1.372 cw(c29.49,-1.752) 29.87,-1.753 29.87,-5.207 cw(c29.185,-5.208) 29.184,-5.893 23.514,-5.894 cw(c23.513,-4.805) 22.743,-5.575 ccw(c22.165,-6.15) 22.163,-5.334 21.844,-5.334
BRA on Top "TOP_BRa" (solid, pour order 19): 15.367,8.462 15.367,12.907 11.459,12.907 ccw(c11.459,12.282) 10.834,12.282 10.834,9.271 ccw(c11.977,9.271) 11.977,8.128 15.033,8.128

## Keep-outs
Keep-Out Layer:
  the board outline again, w0.102

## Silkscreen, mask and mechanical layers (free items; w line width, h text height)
Top Overlay:
  text "VS" at 32.436,12.256 h0.89
  text "VCC_IO" at 1.905,12.042 h1.02
  text "GND" at 1.905,9.502 h1.02
  text "GND" at 31.572,9.182 h0.89
  text "SDO" at 1.905,7.112 h1.02
  text "A1" at 32.342,7.112 h1.02
  text "SDI" at 1.905,4.572 h1.02
  text "A2" at 32.004,4.572 h1.02
  text "SCK" at 1.905,2.032 h1.02
  text "B1" at 32.342,2.032 h1.02
  text "CSN" at 1.905,-0.508 h1.02
  text "B2" at 32.004,-0.508 h1.02
  text "GND" at 1.905,-3.048 h1.02
  text "GND" at 30.988,-3.048 h1.02
  text "'.BoardName'_V'.BoardVersion'" at 7.518,-3.607 h0.89 r90
  text "DRV_ENN" at 1.905,-5.359 h0.84
  text "STEP" at 30.836,-5.74 h0.84
  text "CLK16" at 1.905,-8.128 h1.02
  text "DIR" at 31.157,-8.128 h1.02
  text "SG_TST" at 1.905,-10.668 h1.02
  text "GND" at 30.988,-10.668 h1.02
Bottom Overlay:
  text "VS" at 33.696,12.192 h1.02
  text "VCC_IO" at 7.491,12.042 h1.02
  text "GND" at 33.696,9.652 h1.02
  text "GND" at 4.613,9.502 h1.02
  text "SDO" at 4.613,7.112 h1.02
  text "A1" at 33.696,7.112 h1.02
  text "SDI" at 4.275,4.572 h1.02
  text "A2" at 33.696,4.572 h1.02
  text "SCK" at 4.613,2.032 h1.02
  text "B1" at 33.696,2.032 h1.02
  text "CSN" at 4.613,-0.508 h1.02
  text "B2" at 33.696,-0.508 h1.02
  text "GND" at 4.613,-3.048 h1.02
  text "GND" at 33.696,-3.048 h1.02
  text "DRV_ENN" at 7.491,-5.359 h0.84
  text "STEP" at 33.696,-5.588 h1.02
  text "'.BoardName'_V'.BoardVersion'" at 25.889,-6.526 h0.89
  text "CLK16" at 6.476,-8.128 h1.02
  text "DIR" at 33.696,-8.128 h1.02
  text "IC name: '.Chip'" at 26.01,-8.28 h1.27
  text "Supply range: VS = '.VS'" at 26.012,-9.272 h1.27
  text "Max. current: IRMS = '.IRMS'" at 26.01,-10.363 h1.27
  text "SG_TST" at 7.66,-10.668 h1.02
  text "GND" at 33.696,-10.668 h1.02
TopAsm:
  text "'.BoardName'_V'.BoardVersion'" at 4.596,-8.603 h1.27 r90

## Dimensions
35.83,-11.43 to 35.83,13.97 on Dimension
-1.27,12.97 to 36.83,12.97 on Dimension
